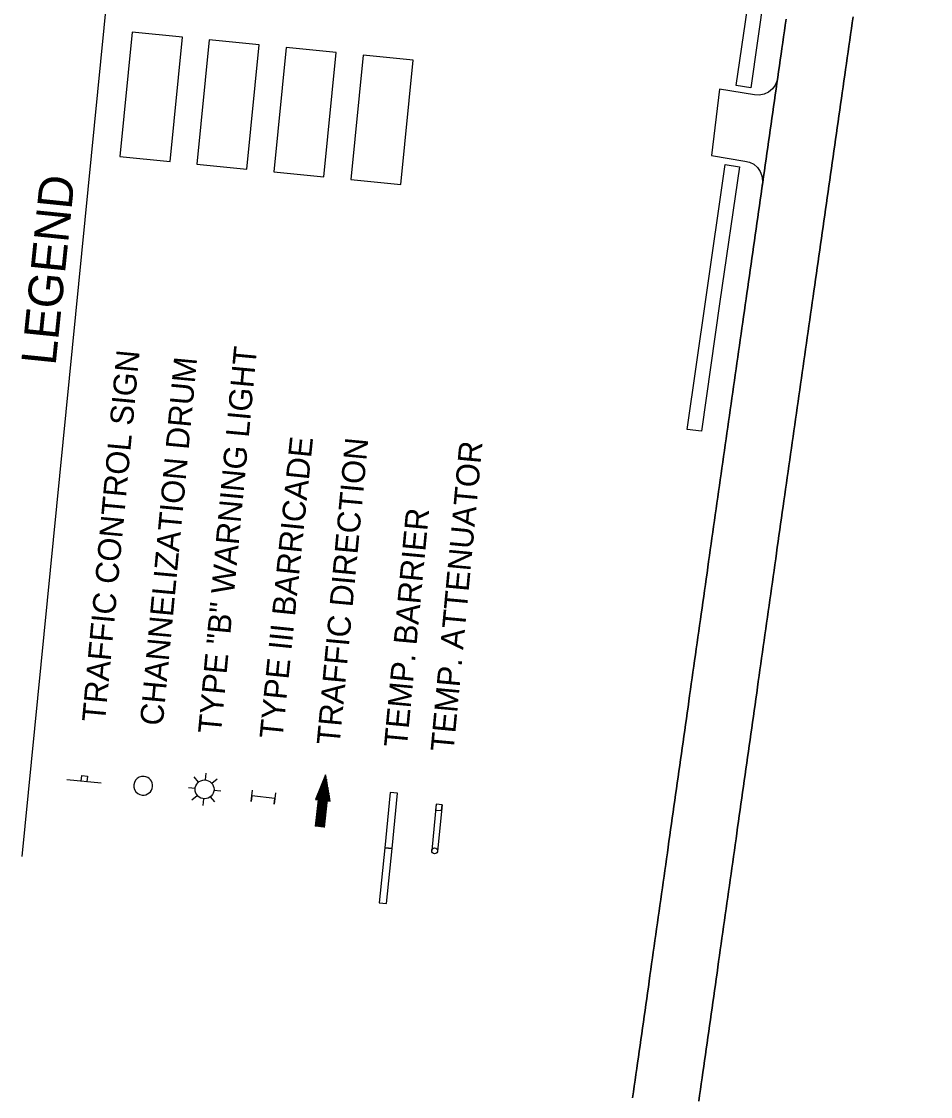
# Model space of a CAD drawing. Extents: x 1795987 to 1799689, y 243690 to 251545.
# Drawn here: x 1797261.2 to 1797568.7, y 247089.3 to 247453.1 of the extents above; entities that cross this region are included whole.
import ezdxf

# ---------------------------------------------------------------- set-up
doc = ezdxf.new("R2010")
doc.units = 0
for name, color, linetype in [('EP', 7, 'Continuous'), ('LEGEND', 7, 'Continuous'), ('Level 23', 7, 'Continuous'), ('Level 62', 7, 'Continuous')]:
    doc.layers.add(name, color=color, linetype=linetype)

# ---------------------------------------------------------------- blocks, each defined once
blk = doc.blocks.new('T21LR')
at = {"layer": 'Level 23'}
for p, q in [((0, 2), (31.5, 2)), ((0, -2), (31.5, -2))]:
    blk.add_line(p, q, dxfattribs=at)
blk.add_lwpolyline([(0, -2), (4, -2), (4, 2), (0, 2)], close=True, dxfattribs=at)
blk.add_circle((31.5, 0), 2, dxfattribs=at)

msp = doc.modelspace()

# ---------------------------------------------------------------- linework, layer by layer
at = {"layer": 'EP'}
for p, q in [((1797507.92, 247430.67), (1797502.98, 247431.42)), ((1797499.19, 247404.72), (1797504.07, 247403.85)), ((1797491.2, 247314.5), (1797486.32, 247315.04))]:
    msp.add_line(p, q, dxfattribs=at)
for points in [[(1797568.69, 247854.47), (1797561.87, 247807.43), (1797555.34, 247761.13), (1797548.75, 247715.15), (1797541.84, 247667.67), (1797535.11, 247620.83), (1797528.62, 247575.39), (1797524.96, 247549.93), (1797525.06, 247548.02), (1797525.55, 247543.91), (1797526.45, 247539.86), (1797526.65, 247538.96), (1797527.41, 247535.59), (1797527.98, 247531.38), (1797528.16, 247527.13), (1797526.97, 247518.48), (1797526.28, 247516.25), (1797524.64, 247511.95), (1797522.63, 247507.8), (1797522.17, 247506.93), (1797521.53, 247505.59), (1797517.43, 247496.48), (1797514.72, 247478.52), (1797507.92, 247430.67)], [(1797502.98, 247431.42), (1797509.89, 247479.28)], [(1797486.32, 247315.04), (1797492.66, 247359.05), (1797499.19, 247404.72)], [(1797504.07, 247403.85), (1797497.45, 247358.32), (1797491.2, 247314.5)]]:
    msp.add_lwpolyline(points, dxfattribs=at)
at = {"layer": 'LEGEND'}
for p, q in [((1797261.35, 247170.53), (1797308.29, 247644.28)), ((1797323.41, 247196.41), (1797323.64, 247198.71)), ((1797288.14, 247195.31), (1797276.49, 247196.46)), ((1797321.07, 247195.7), (1797319.61, 247197.49)), ((1797327.36, 247196.72), (1797325.57, 247195.26)), ((1797364.05, 247198.17), (1797360.6, 247189.86)), ((1797365.57, 247189.3), (1797364.05, 247198.17)), ((1797319.92, 247193.55), (1797317.62, 247193.78)), ((1797318.84, 247189.74), (1797320.63, 247191.21)), ((1797326.28, 247192.92), (1797328.58, 247192.69)), ((1797322.78, 247190.06), (1797322.55, 247187.76)), ((1797326.59, 247188.98), (1797325.12, 247190.76)), ((1797361.53, 247189.75), (1797360.52, 247180.73)), ((1797360.6, 247189.86), (1797361.53, 247189.75)), ((1797363.62, 247180.38), (1797364.63, 247189.4)), ((1797364.63, 247189.4), (1797365.57, 247189.3))]:
    msp.add_line(p, q, dxfattribs=at)
for points in [[(1797311.42, 247405.67), (1797315.58, 247447.74), (1797298.6, 247449.42), (1797294.43, 247407.35)], [(1797337.45, 247403.09), (1797341.62, 247445.16), (1797324.63, 247446.84), (1797320.46, 247404.77)], [(1797363.49, 247400.51), (1797367.66, 247442.58), (1797350.67, 247444.26), (1797346.5, 247402.19)], [(1797389.53, 247397.93), (1797393.69, 247440), (1797376.71, 247441.68), (1797372.54, 247399.61)], [(1797281.34, 247195.98), (1797281.54, 247197.92), (1797283.48, 247197.73), (1797283.28, 247195.79)], [(1797388.37, 247191.9), (1797385.88, 247192.14), (1797384.04, 247173.48), (1797386.53, 247173.24)], [(1797386.53, 247173.24), (1797384.04, 247173.48), (1797382.19, 247154.83), (1797384.68, 247154.58)]]:
    msp.add_lwpolyline(points, close=True, dxfattribs=at)
for points in [[(1797362.84, 247195.26), (1797361.2, 247180.65)], [(1797363.2, 247196.12), (1797361.45, 247180.62)], [(1797363.56, 247196.99), (1797361.71, 247180.59)], [(1797363.91, 247197.85), (1797361.97, 247180.56)], [(1797364.15, 247197.6), (1797362.23, 247180.53)], [(1797364.31, 247196.68), (1797362.49, 247180.5)], [(1797364.46, 247195.75), (1797362.75, 247180.48)], [(1797364.62, 247194.83), (1797363, 247180.45)], [(1797347.12, 247192.11), (1797346.67, 247188.24), (1797346.89, 247190.18), (1797339.14, 247191.08), (1797338.92, 247189.14), (1797339.37, 247193.01)], [(1797362.12, 247193.53), (1797360.68, 247180.71)], [(1797361.04, 247190.94), (1797360.92, 247189.82)], [(1797362.48, 247194.39), (1797360.94, 247180.68)], [(1797361.4, 247191.8), (1797361.18, 247189.79)], [(1797361.76, 247192.67), (1797361.44, 247189.76)], [(1797364.78, 247193.91), (1797363.26, 247180.42)], [(1797364.94, 247192.99), (1797363.52, 247180.39)], [(1797365.1, 247192.06), (1797364.79, 247189.38)], [(1797365.25, 247191.14), (1797365.05, 247189.35)], [(1797360.69, 247190.07), (1797360.66, 247189.85)], [(1797365.41, 247190.22), (1797365.31, 247189.33)]]:
    msp.add_lwpolyline(points, dxfattribs=at)
msp.add_circle((1797323.1, 247193.23), 3.19, dxfattribs=at)
for start, end in [(84.3414, 264.3414), (264.3414, 84.3414)]:
    msp.add_arc((1797302.33, 247194.48), 3.18, start, end, dxfattribs=at)
at = {"layer": 'Level 62'}
for points in [[(1797467.89, 247088.91), (1797468.17, 247090.87), (1797468.45, 247092.84), (1797468.74, 247094.8), (1797469.02, 247096.77), (1797469.3, 247098.73), (1797469.59, 247100.7), (1797469.87, 247102.67), (1797470.15, 247104.63), (1797470.43, 247106.6), (1797470.72, 247108.56), (1797471, 247110.54), (1797471.28, 247112.51), (1797471.56, 247114.49), (1797471.84, 247116.46), (1797472.11, 247118.43), (1797472.39, 247120.41), (1797472.67, 247122.38), (1797472.95, 247124.35), (1797473.23, 247126.33), (1797473.51, 247128.3), (1797473.79, 247130.27), (1797474.07, 247132.25), (1797474.35, 247134.22), (1797474.63, 247136.19), (1797474.91, 247138.17), (1797475.19, 247140.14), (1797475.47, 247142.12), (1797475.75, 247144.09), (1797476.03, 247146.06), (1797476.31, 247148.04), (1797476.59, 247150.01), (1797476.87, 247151.98), (1797477.15, 247153.96), (1797477.42, 247155.93), (1797477.7, 247157.9), (1797477.98, 247159.88), (1797478.26, 247161.85), (1797478.54, 247163.83), (1797478.82, 247165.8), (1797479.1, 247167.77), (1797479.38, 247169.75), (1797479.66, 247171.72), (1797479.94, 247173.69), (1797480.22, 247175.67), (1797480.5, 247177.64), (1797480.78, 247179.61), (1797481.06, 247181.59), (1797481.34, 247183.56), (1797481.62, 247185.54), (1797481.9, 247187.51), (1797482.18, 247189.48), (1797482.46, 247191.46), (1797482.74, 247193.43), (1797483.01, 247195.4), (1797483.29, 247197.38), (1797483.57, 247199.35), (1797483.85, 247201.32), (1797484.13, 247203.3), (1797484.41, 247205.27), (1797484.69, 247207.25), (1797484.97, 247209.22), (1797485.25, 247211.19), (1797485.53, 247213.17), (1797485.81, 247215.14), (1797486.09, 247217.11), (1797486.37, 247219.09), (1797486.65, 247221.06), (1797486.93, 247223.03), (1797487.21, 247225.01), (1797487.49, 247226.98), (1797487.77, 247228.96), (1797488.05, 247230.93), (1797488.32, 247232.9), (1797488.6, 247234.88), (1797488.88, 247236.85), (1797489.16, 247238.82), (1797489.44, 247240.8), (1797489.72, 247242.77), (1797490, 247244.74), (1797490.28, 247246.72), (1797490.56, 247248.69), (1797490.84, 247250.67), (1797491.12, 247252.64), (1797491.4, 247254.61), (1797491.68, 247256.59), (1797491.96, 247258.56), (1797492.24, 247260.53), (1797492.52, 247262.51), (1797492.8, 247264.48), (1797493.08, 247266.45), (1797493.36, 247268.43), (1797493.63, 247270.4), (1797493.91, 247272.38), (1797494.19, 247274.35), (1797494.47, 247276.32), (1797494.76, 247278.3), (1797495.04, 247280.27), (1797495.32, 247282.24), (1797495.6, 247284.21), (1797495.88, 247286.19), (1797496.16, 247288.16), (1797496.44, 247290.13), (1797496.73, 247292.1), (1797497.01, 247294.08), (1797497.29, 247296.05), (1797497.57, 247298.02), (1797497.85, 247300), (1797498.13, 247301.97), (1797498.42, 247303.94), (1797498.7, 247305.91), (1797498.98, 247307.89), (1797499.26, 247309.86), (1797499.54, 247311.83), (1797499.82, 247313.8), (1797500.11, 247315.78), (1797500.39, 247317.75), (1797500.67, 247319.72), (1797500.95, 247321.7), (1797501.23, 247323.67), (1797501.51, 247325.64), (1797501.8, 247327.61), (1797502.08, 247329.59), (1797502.36, 247331.56), (1797502.64, 247333.53), (1797502.92, 247335.5), (1797503.2, 247337.48), (1797503.48, 247339.45), (1797503.77, 247341.42), (1797504.05, 247343.39), (1797504.33, 247345.37), (1797504.61, 247347.34), (1797504.89, 247349.31), (1797505.17, 247351.29), (1797505.46, 247353.26), (1797505.74, 247355.23), (1797506.02, 247357.2), (1797506.3, 247359.18), (1797506.58, 247361.15), (1797506.86, 247363.12), (1797507.15, 247365.09), (1797507.43, 247367.07), (1797507.71, 247369.04), (1797507.99, 247371.01), (1797508.27, 247372.99), (1797508.55, 247374.96), (1797508.84, 247376.93), (1797509.12, 247378.9), (1797509.4, 247380.88), (1797509.68, 247382.85), (1797509.96, 247384.82), (1797510.24, 247386.79), (1797510.52, 247388.77), (1797510.81, 247390.74), (1797511.09, 247392.71), (1797511.37, 247394.69), (1797511.65, 247396.66), (1797511.93, 247398.63), (1797512.21, 247400.6), (1797512.5, 247402.58), (1797512.78, 247404.55), (1797513.06, 247406.52), (1797513.34, 247408.49), (1797513.62, 247410.47), (1797513.9, 247412.44), (1797514.19, 247414.41), (1797514.47, 247416.39), (1797514.75, 247418.36), (1797515.03, 247420.33), (1797515.31, 247422.3), (1797515.59, 247424.28), (1797515.88, 247426.25), (1797516.16, 247428.22), (1797516.44, 247430.19), (1797516.72, 247432.17), (1797517, 247434.14), (1797517.28, 247436.11), (1797517.57, 247438.09), (1797517.85, 247440.06), (1797518.13, 247442.03), (1797518.41, 247444), (1797518.69, 247445.98), (1797518.97, 247447.95), (1797519.25, 247449.92), (1797519.54, 247451.89), (1797519.82, 247453.87)], [(1797519.82, 247453.87), (1797519.54, 247451.89), (1797519.25, 247449.92), (1797518.97, 247447.95), (1797518.69, 247445.98), (1797518.41, 247444), (1797518.13, 247442.03), (1797517.85, 247440.06), (1797517.57, 247438.09), (1797517.28, 247436.11), (1797517, 247434.14), (1797516.72, 247432.17), (1797516.44, 247430.19), (1797516.16, 247428.22), (1797515.88, 247426.25), (1797515.59, 247424.28), (1797515.31, 247422.3), (1797515.03, 247420.33), (1797514.75, 247418.36), (1797514.47, 247416.39), (1797514.19, 247414.41), (1797513.9, 247412.44), (1797513.62, 247410.47), (1797513.34, 247408.49), (1797513.06, 247406.52), (1797512.78, 247404.55), (1797512.5, 247402.58), (1797512.21, 247400.6), (1797511.93, 247398.63), (1797511.65, 247396.66), (1797511.37, 247394.69), (1797511.09, 247392.71), (1797510.81, 247390.74), (1797510.52, 247388.77), (1797510.24, 247386.79), (1797509.96, 247384.82), (1797509.68, 247382.85), (1797509.4, 247380.88), (1797509.12, 247378.9), (1797508.84, 247376.93), (1797508.55, 247374.96), (1797508.27, 247372.99), (1797507.99, 247371.01), (1797507.71, 247369.04), (1797507.43, 247367.07), (1797507.15, 247365.09), (1797506.86, 247363.12), (1797506.58, 247361.15), (1797506.3, 247359.18), (1797506.02, 247357.2), (1797505.74, 247355.23), (1797505.46, 247353.26), (1797505.17, 247351.29), (1797504.89, 247349.31), (1797504.61, 247347.34), (1797504.33, 247345.37), (1797504.05, 247343.39), (1797503.77, 247341.42), (1797503.48, 247339.45), (1797503.2, 247337.48), (1797502.92, 247335.5), (1797502.64, 247333.53), (1797502.36, 247331.56), (1797502.08, 247329.59), (1797501.8, 247327.61), (1797501.51, 247325.64), (1797501.23, 247323.67), (1797500.95, 247321.7), (1797500.67, 247319.72), (1797500.39, 247317.75), (1797500.11, 247315.78), (1797499.82, 247313.8), (1797499.54, 247311.83), (1797499.26, 247309.86), (1797498.98, 247307.89), (1797498.7, 247305.91), (1797498.42, 247303.94), (1797498.13, 247301.97), (1797497.85, 247300), (1797497.57, 247298.02), (1797497.29, 247296.05), (1797497.01, 247294.08), (1797496.73, 247292.1), (1797496.44, 247290.13), (1797496.16, 247288.16), (1797495.88, 247286.19), (1797495.6, 247284.21), (1797495.32, 247282.24), (1797495.04, 247280.27), (1797494.76, 247278.3), (1797494.47, 247276.32), (1797494.19, 247274.35), (1797493.91, 247272.38), (1797493.63, 247270.4), (1797493.36, 247268.43), (1797493.08, 247266.45), (1797492.8, 247264.48), (1797492.52, 247262.51), (1797492.24, 247260.53), (1797491.96, 247258.56), (1797491.68, 247256.59), (1797491.4, 247254.61), (1797491.12, 247252.64), (1797490.84, 247250.67), (1797490.56, 247248.69), (1797490.28, 247246.72), (1797490, 247244.74), (1797489.72, 247242.77), (1797489.44, 247240.8), (1797489.16, 247238.82), (1797488.88, 247236.85), (1797488.6, 247234.88), (1797488.32, 247232.9), (1797488.05, 247230.93), (1797487.77, 247228.96), (1797487.49, 247226.98), (1797487.21, 247225.01), (1797486.93, 247223.03), (1797486.65, 247221.06), (1797486.37, 247219.09), (1797486.09, 247217.11), (1797485.81, 247215.14), (1797485.53, 247213.17), (1797485.25, 247211.19), (1797484.97, 247209.22), (1797484.69, 247207.25), (1797484.41, 247205.27), (1797484.13, 247203.3), (1797483.85, 247201.32), (1797483.57, 247199.35), (1797483.29, 247197.38), (1797483.01, 247195.4), (1797482.74, 247193.43), (1797482.46, 247191.46), (1797482.18, 247189.48), (1797481.9, 247187.51), (1797481.62, 247185.54), (1797481.34, 247183.56), (1797481.06, 247181.59), (1797480.78, 247179.61), (1797480.5, 247177.64), (1797480.22, 247175.67), (1797479.94, 247173.69), (1797479.66, 247171.72), (1797479.38, 247169.75), (1797479.1, 247167.77), (1797478.82, 247165.8), (1797478.54, 247163.83), (1797478.26, 247161.85), (1797477.98, 247159.88), (1797477.7, 247157.9), (1797477.42, 247155.93), (1797477.15, 247153.96), (1797476.87, 247151.98), (1797476.59, 247150.01), (1797476.31, 247148.04), (1797476.03, 247146.06), (1797475.75, 247144.09), (1797475.47, 247142.12), (1797475.19, 247140.14), (1797474.91, 247138.17), (1797474.63, 247136.19), (1797474.35, 247134.22), (1797474.07, 247132.25), (1797473.79, 247130.27), (1797473.51, 247128.3), (1797473.23, 247126.33), (1797472.95, 247124.35), (1797472.67, 247122.38), (1797472.39, 247120.41), (1797472.11, 247118.43), (1797471.84, 247116.46), (1797471.56, 247114.49), (1797471.28, 247112.51), (1797471, 247110.54), (1797470.72, 247108.56), (1797470.43, 247106.6), (1797470.15, 247104.63), (1797469.87, 247102.67), (1797469.59, 247100.7), (1797469.3, 247098.73), (1797469.02, 247096.77), (1797468.74, 247094.8), (1797468.45, 247092.84), (1797468.17, 247090.87), (1797467.89, 247088.91)], [(1797542.49, 247454.65), (1797542.21, 247452.67), (1797541.93, 247450.7), (1797541.65, 247448.73), (1797541.36, 247446.76), (1797541.08, 247444.78), (1797540.8, 247442.81), (1797540.52, 247440.84), (1797540.24, 247438.87), (1797539.96, 247436.89), (1797539.67, 247434.92), (1797539.39, 247432.95), (1797539.11, 247430.98), (1797538.83, 247429), (1797538.55, 247427.03), (1797538.27, 247425.06), (1797537.99, 247423.09), (1797537.7, 247421.11), (1797537.42, 247419.14), (1797537.14, 247417.17), (1797536.86, 247415.2), (1797536.58, 247413.22), (1797536.3, 247411.25), (1797536.01, 247409.28), (1797535.73, 247407.31), (1797535.45, 247405.33), (1797535.17, 247403.36), (1797534.89, 247401.39), (1797534.61, 247399.42), (1797534.32, 247397.44), (1797534.04, 247395.47), (1797533.76, 247393.5), (1797533.48, 247391.53), (1797533.2, 247389.56), (1797532.92, 247387.58), (1797532.64, 247385.61), (1797532.35, 247383.64), (1797532.07, 247381.67), (1797531.79, 247379.69), (1797531.51, 247377.72), (1797531.23, 247375.75), (1797530.95, 247373.78), (1797530.66, 247371.8), (1797530.38, 247369.83), (1797530.1, 247367.86), (1797529.82, 247365.89), (1797529.54, 247363.91), (1797529.26, 247361.94), (1797528.98, 247359.97), (1797528.69, 247358), (1797528.41, 247356.02), (1797528.13, 247354.05), (1797527.85, 247352.08), (1797527.57, 247350.11), (1797527.29, 247348.13), (1797527, 247346.16), (1797526.72, 247344.19), (1797526.44, 247342.22), (1797526.16, 247340.24), (1797525.88, 247338.27), (1797525.6, 247336.3), (1797525.31, 247334.33), (1797525.03, 247332.35), (1797524.75, 247330.38), (1797524.47, 247328.41), (1797524.19, 247326.44), (1797523.91, 247324.46), (1797523.63, 247322.49), (1797523.34, 247320.52), (1797523.06, 247318.55), (1797522.78, 247316.57), (1797522.5, 247314.6), (1797522.22, 247312.63), (1797521.94, 247310.66), (1797521.65, 247308.68), (1797521.37, 247306.71), (1797521.09, 247304.74), (1797520.81, 247302.77), (1797520.53, 247300.79), (1797520.25, 247298.82), (1797519.96, 247296.85), (1797519.68, 247294.88), (1797519.4, 247292.9), (1797519.12, 247290.93), (1797518.84, 247288.96), (1797518.56, 247286.99), (1797518.28, 247285.01), (1797517.99, 247283.04), (1797517.71, 247281.07), (1797517.43, 247279.1), (1797517.15, 247277.12), (1797516.87, 247275.15), (1797516.59, 247273.18), (1797516.31, 247271.21), (1797516.03, 247269.23), (1797515.75, 247267.26), (1797515.47, 247265.28), (1797515.19, 247263.31), (1797514.91, 247261.34), (1797514.63, 247259.36), (1797514.35, 247257.39), (1797514.07, 247255.41), (1797513.79, 247253.44), (1797513.51, 247251.47), (1797513.23, 247249.49), (1797512.95, 247247.52), (1797512.67, 247245.55), (1797512.39, 247243.57), (1797512.11, 247241.6), (1797511.83, 247239.62), (1797511.55, 247237.65), (1797511.28, 247235.68), (1797511, 247233.7), (1797510.72, 247231.73), (1797510.44, 247229.76), (1797510.16, 247227.78), (1797509.88, 247225.81), (1797509.6, 247223.83), (1797509.32, 247221.86), (1797509.04, 247219.89), (1797508.76, 247217.91), (1797508.48, 247215.94), (1797508.2, 247213.97), (1797507.92, 247211.99), (1797507.64, 247210.02), (1797507.36, 247208.04), (1797507.08, 247206.07), (1797506.8, 247204.1), (1797506.52, 247202.12), (1797506.24, 247200.15), (1797505.96, 247198.18), (1797505.69, 247196.2), (1797505.41, 247194.23), (1797505.13, 247192.25), (1797504.85, 247190.28), (1797504.57, 247188.31), (1797504.29, 247186.33), (1797504.01, 247184.36), (1797503.73, 247182.39), (1797503.45, 247180.41), (1797503.17, 247178.44), (1797502.89, 247176.46), (1797502.61, 247174.49), (1797502.33, 247172.52), (1797502.05, 247170.54), (1797501.77, 247168.57), (1797501.49, 247166.6), (1797501.21, 247164.62), (1797500.93, 247162.65), (1797500.65, 247160.67), (1797500.37, 247158.7), (1797500.1, 247156.73), (1797499.82, 247154.75), (1797499.54, 247152.78), (1797499.26, 247150.8), (1797498.98, 247148.83), (1797498.7, 247146.86), (1797498.42, 247144.88), (1797498.14, 247142.91), (1797497.86, 247140.94), (1797497.58, 247138.96), (1797497.3, 247136.99), (1797497.02, 247135.01), (1797496.74, 247133.04), (1797496.46, 247131.07), (1797496.18, 247129.09), (1797495.9, 247127.12), (1797495.62, 247125.15), (1797495.34, 247123.17), (1797495.06, 247121.2), (1797494.78, 247119.22), (1797494.51, 247117.25), (1797494.23, 247115.28), (1797493.95, 247113.3), (1797493.67, 247111.33), (1797493.39, 247109.36), (1797493.11, 247107.38), (1797492.83, 247105.41), (1797492.55, 247103.44), (1797492.26, 247101.48), (1797491.98, 247099.51), (1797491.7, 247097.54), (1797491.41, 247095.58), (1797491.13, 247093.61), (1797490.85, 247091.65), (1797490.57, 247089.68), (1797490.28, 247087.72)], [(1797490.28, 247087.72), (1797490.57, 247089.68), (1797490.85, 247091.65), (1797491.13, 247093.61), (1797491.41, 247095.58), (1797491.7, 247097.54), (1797491.98, 247099.51), (1797492.26, 247101.48), (1797492.55, 247103.44), (1797492.83, 247105.41), (1797493.11, 247107.38), (1797493.39, 247109.36), (1797493.67, 247111.33), (1797493.95, 247113.3), (1797494.23, 247115.28), (1797494.51, 247117.25), (1797494.78, 247119.22), (1797495.06, 247121.2), (1797495.34, 247123.17), (1797495.62, 247125.15), (1797495.9, 247127.12), (1797496.18, 247129.09), (1797496.46, 247131.07), (1797496.74, 247133.04), (1797497.02, 247135.01), (1797497.3, 247136.99), (1797497.58, 247138.96), (1797497.86, 247140.94), (1797498.14, 247142.91), (1797498.42, 247144.88), (1797498.7, 247146.86), (1797498.98, 247148.83), (1797499.26, 247150.8), (1797499.54, 247152.78), (1797499.82, 247154.75), (1797500.1, 247156.73), (1797500.37, 247158.7), (1797500.65, 247160.67), (1797500.93, 247162.65), (1797501.21, 247164.62), (1797501.49, 247166.6), (1797501.77, 247168.57), (1797502.05, 247170.54), (1797502.33, 247172.52), (1797502.61, 247174.49), (1797502.89, 247176.46), (1797503.17, 247178.44), (1797503.45, 247180.41), (1797503.73, 247182.39), (1797504.01, 247184.36), (1797504.29, 247186.33), (1797504.57, 247188.31), (1797504.85, 247190.28), (1797505.13, 247192.25), (1797505.41, 247194.23), (1797505.69, 247196.2), (1797505.96, 247198.18), (1797506.24, 247200.15), (1797506.52, 247202.12), (1797506.8, 247204.1), (1797507.08, 247206.07), (1797507.36, 247208.04), (1797507.64, 247210.02), (1797507.92, 247211.99), (1797508.2, 247213.97), (1797508.48, 247215.94), (1797508.76, 247217.91), (1797509.04, 247219.89), (1797509.32, 247221.86), (1797509.6, 247223.83), (1797509.88, 247225.81), (1797510.16, 247227.78), (1797510.44, 247229.76), (1797510.72, 247231.73), (1797511, 247233.7), (1797511.28, 247235.68), (1797511.55, 247237.65), (1797511.83, 247239.62), (1797512.11, 247241.6), (1797512.39, 247243.57), (1797512.67, 247245.55), (1797512.95, 247247.52), (1797513.23, 247249.49), (1797513.51, 247251.47), (1797513.79, 247253.44), (1797514.07, 247255.41), (1797514.35, 247257.39), (1797514.63, 247259.36), (1797514.91, 247261.34), (1797515.19, 247263.31), (1797515.47, 247265.28), (1797515.75, 247267.26), (1797516.03, 247269.23), (1797516.31, 247271.21), (1797516.59, 247273.18), (1797516.87, 247275.15), (1797517.15, 247277.12), (1797517.43, 247279.1), (1797517.71, 247281.07), (1797517.99, 247283.04), (1797518.28, 247285.01), (1797518.56, 247286.99), (1797518.84, 247288.96), (1797519.12, 247290.93), (1797519.4, 247292.9), (1797519.68, 247294.88), (1797519.96, 247296.85), (1797520.25, 247298.82), (1797520.53, 247300.79), (1797520.81, 247302.77), (1797521.09, 247304.74), (1797521.37, 247306.71), (1797521.65, 247308.68), (1797521.94, 247310.66), (1797522.22, 247312.63), (1797522.5, 247314.6), (1797522.78, 247316.57), (1797523.06, 247318.55), (1797523.34, 247320.52), (1797523.63, 247322.49), (1797523.91, 247324.46), (1797524.19, 247326.44), (1797524.47, 247328.41), (1797524.75, 247330.38), (1797525.03, 247332.35), (1797525.31, 247334.33), (1797525.6, 247336.3), (1797525.88, 247338.27), (1797526.16, 247340.24), (1797526.44, 247342.22), (1797526.72, 247344.19), (1797527, 247346.16), (1797527.29, 247348.13), (1797527.57, 247350.11), (1797527.85, 247352.08), (1797528.13, 247354.05), (1797528.41, 247356.02), (1797528.69, 247358), (1797528.98, 247359.97), (1797529.26, 247361.94), (1797529.54, 247363.91), (1797529.82, 247365.89), (1797530.1, 247367.86), (1797530.38, 247369.83), (1797530.66, 247371.8), (1797530.95, 247373.78), (1797531.23, 247375.75), (1797531.51, 247377.72), (1797531.79, 247379.69), (1797532.07, 247381.67), (1797532.35, 247383.64), (1797532.64, 247385.61), (1797532.92, 247387.58), (1797533.2, 247389.56), (1797533.48, 247391.53), (1797533.76, 247393.5), (1797534.04, 247395.47), (1797534.32, 247397.44), (1797534.61, 247399.42), (1797534.89, 247401.39), (1797535.17, 247403.36), (1797535.45, 247405.33), (1797535.73, 247407.31), (1797536.01, 247409.28), (1797536.3, 247411.25), (1797536.58, 247413.22), (1797536.86, 247415.2), (1797537.14, 247417.17), (1797537.42, 247419.14), (1797537.7, 247421.11), (1797537.99, 247423.09), (1797538.27, 247425.06), (1797538.55, 247427.03), (1797538.83, 247429), (1797539.11, 247430.98), (1797539.39, 247432.95), (1797539.67, 247434.92), (1797539.96, 247436.89), (1797540.24, 247438.87), (1797540.52, 247440.84), (1797540.8, 247442.81), (1797541.08, 247444.78), (1797541.36, 247446.76), (1797541.65, 247448.73), (1797541.93, 247450.7), (1797542.21, 247452.67), (1797542.49, 247454.65)], [(1797346.5, 247402.19), (1797363.49, 247400.51), (1797367.66, 247442.58), (1797350.67, 247444.26), (1797346.5, 247402.19)], [(1797516.85, 247433.11), (1797516.85, 247433.11), (1797516.19, 247431.59), (1797515.19, 247430.26), (1797513.9, 247429.22), (1797512.4, 247428.51), (1797510.78, 247428.18), (1797509.12, 247428.24), (1797497.35, 247430.15), (1797494.65, 247407.73), (1797505.83, 247405.84), (1797507.43, 247405.49), (1797508.89, 247404.75), (1797510.13, 247403.69), (1797511.08, 247402.36), (1797511.67, 247400.84), (1797511.88, 247399.22), (1797511.69, 247397.59), (1797511.78, 247397.58), (1797511.93, 247398.63), (1797512.21, 247400.6), (1797512.5, 247402.58), (1797512.78, 247404.55), (1797513.06, 247406.52), (1797513.34, 247408.49), (1797513.62, 247410.47), (1797513.9, 247412.44), (1797514.19, 247414.41), (1797514.47, 247416.39), (1797514.75, 247418.36), (1797515.03, 247420.33), (1797515.31, 247422.3), (1797515.59, 247424.28), (1797515.88, 247426.25), (1797516.16, 247428.22), (1797516.44, 247430.19), (1797516.72, 247432.17), (1797516.85, 247433.11)]]:
    msp.add_lwpolyline(points, dxfattribs=at)

# ---------------------------------------------------------------- block references
at = {"layer": 'LEGEND', "xscale": 0.5000000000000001, "yscale": 0.5000000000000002, "rotation": -95.50928026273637}
msp.add_blockref('T21LR', (1797402.45, 247188.12), dxfattribs=at)

# ---------------------------------------------------------------- texts
at = {"layer": 'LEGEND'}
for s, height, rotation, p in [('LEGEND', 11.7, 84.1754, (1797272.68, 247336.47)), ('TRAFFIC CONTROL SIGN', 7.7999, 84.6544, (1797289.39, 247215.75)), ('TYPE "B" WARNING LIGHT', 7.7999, 84.6544, (1797328.64, 247211.85)), ('CHANNELIZATION DRUM', 7.7999, 84.6544, (1797308.94, 247214.55)), ('TYPE III BARRICADE', 7.7999, 84.1754, (1797349.42, 247210.1)), ('TRAFFIC DIRECTION', 7.7999, 84.6544, (1797368.78, 247208.01)), ('TEMP. ATTENUATOR', 7.7999, 84.6544, (1797407.32, 247205.74)), ('TEMP. BARRIER', 7.7999, 84.6544, (1797391.55, 247207.25))]:
    msp.add_text(s, height=height, rotation=rotation, dxfattribs=at).set_placement(p)

doc.saveas('drawing.dxf')
